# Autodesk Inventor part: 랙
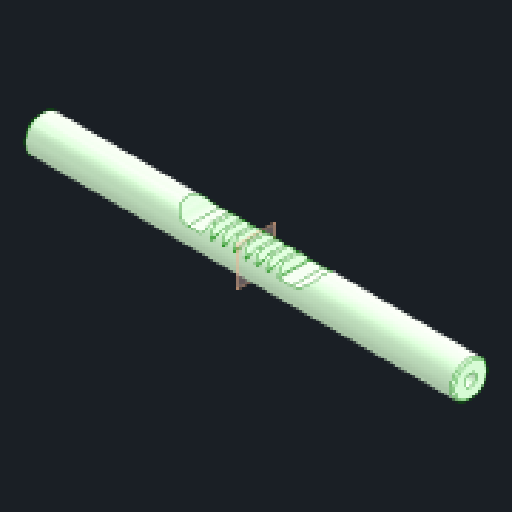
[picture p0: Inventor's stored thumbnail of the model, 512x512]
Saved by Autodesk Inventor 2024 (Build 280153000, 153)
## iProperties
Created: 2024-05
Part Number: 랙
Material: 강철, 탄소
Document SubType Name: Modeling
Designer: kh_501
Density: 7.85 g/cm^3
Appearance: 기본값
Author: jhkim
Sending System: Autodesk Inventor 2025
Preprocessor: ST-DEVELOPER v20
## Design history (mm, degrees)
feature "솔리드1"
node "작업 평면1"
node "솔리드2"
